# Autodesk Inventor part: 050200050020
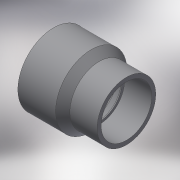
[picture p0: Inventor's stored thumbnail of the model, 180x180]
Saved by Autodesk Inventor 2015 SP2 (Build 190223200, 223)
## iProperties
Created: 2017-10
Part Number: 050200050020
Material: Generic
Description: PLASSON REDUCING SOCKET M.F.50(40)20 CEMENTED
Document SubType Name: Modeling
Designer: KIM
Density: 1 g/cm^3
Appearance: Default
Author: KIM
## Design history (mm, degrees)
derived "050200.ipt"
feature "Solid1::050200.ipt"
tag "TaggingFeature1"
body "Solid1"
other parameters: "d0" = 61, "d1" = 31, "d2" = 16, "d3" = 26, "d5" = 27, "d8" = 18, "d9" = 45 deg, "d12" = 0.4, "L_" = 31, "l_" = 26, "l_1" = 16, "E_" = 27, "H_" = 61, "d11" = 6.87671
